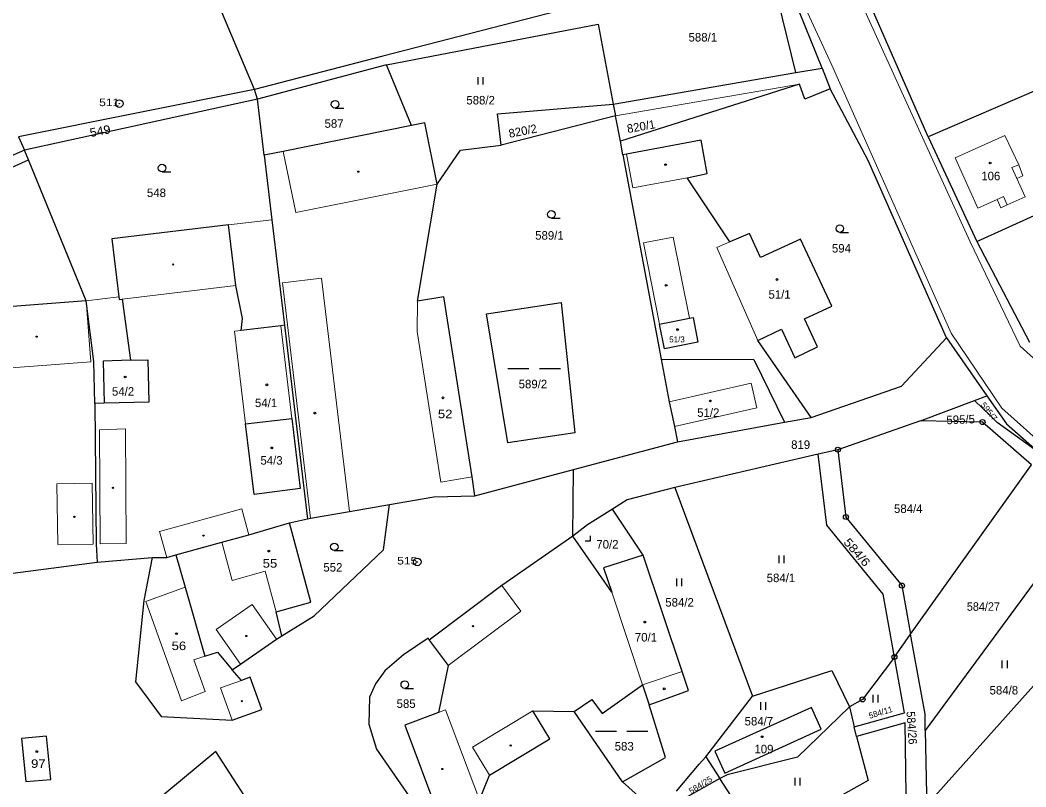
# Model space of a CAD drawing. Extents: x -687135 to -684370, y -1007309 to -1005782.
# Drawn here: x -685221.9 to -685021.3, y -1006597.5 to -1006444.6 of the extents above; entities that cross this region are included whole.
import ezdxf
from ezdxf.enums import TextEntityAlignment as Align

# ---------------------------------------------------------------- set-up
doc = ezdxf.new("R2010")
doc.units = 0
doc.header["$LTSCALE"] = 0.68
for name, color, linetype, lineweight in [('1', 7, 'Continuous', 25), ('3', 7, 'Continuous', 25), ('4', 7, 'Continuous', 13), ('5', 7, 'Continuous', 25), ('8', 7, 'Continuous', 25)]:
    doc.layers.add(name, color=color, linetype=linetype, lineweight=lineweight)
doc.layers.add('2', color=7, linetype='Continuous')

msp = doc.modelspace()

# ---------------------------------------------------------------- linework, layer by layer
at = {"layer": '1'}
for p, q in [((-685148.86, -1006453.5), (-685174.56, -1006460.29)), ((-685143.83, -1006465.57), (-685148.86, -1006453.5)), ((-685067.19, -1006455.02), (-685061.94, -1006454.16)), ((-685061.94, -1006454.16), (-685060.36, -1006458.25)), ((-685103.6, -1006461.29), (-685067.19, -1006455.02)), ((-685174.56, -1006460.29), (-685175.13, -1006458.36)), ((-685103.6, -1006461.29), (-685103.16, -1006463.61)), ((-685208.75, -1006500.55), (-685220.24, -1006472.43)), ((-685031.08, -1006488.72), (-685020.6, -1006508.76)), ((-685131.76, -1006535.66), (-685136.46, -1006505.64)), ((-685037.16, -1006507.9), (-685029.1, -1006519.47)), ((-685042.37, -1006524.46), (-685031.56, -1006520.39)), ((-685031.56, -1006520.39), (-685029.1, -1006519.47)), ((-685069.43, -1006524.75), (-685064.12, -1006523.78)), ((-685090.83, -1006528.68), (-685069.43, -1006524.75)), ((-685058.8, -1006530.22), (-685062.72, -1006531.12)), ((-685111.66, -1006547.46), (-685111.55, -1006534.15)), ((-685044.3, -1006567.02), (-685020.17, -1006533.22)), ((-685091.34, -1006537.79), (-685075.81, -1006579.35)), ((-685097.63, -1006551.25), (-685103.73, -1006542.09)), ((-685237.76, -1006556.75), (-685206.53, -1006552.66)), ((-685097.63, -1006551.25), (-685105.53, -1006553.81)), ((-685047.55, -1006571.57), (-685044.3, -1006567.02)), ((-685055.1, -1006587.45), (-685055.58, -1006585.5)), ((-685150.81, -1006589.92), (-685141.03, -1006604.08)), ((-685085.12, -1006591.49), (-685082.35, -1006595.77))]:
    msp.add_line(p, q, dxfattribs=at)
for points in [[(-685061.94, -1006454.16), (-685073.28, -1006426.13), (-685089.64, -1006391.69), (-685115.59, -1006335.15), (-685153.62, -1006286.74), (-685198.1, -1006232.27)], [(-685175.13, -1006458.36), (-685198.89, -1006402.17), (-685211.49, -1006378.14), (-685237.4, -1006328.81), (-685256.82, -1006291)], [(-685040.8, -1006467.83), (-685055.26, -1006434.88), (-685055.37, -1006434.63), (-685067.76, -1006407.52), (-685091.4, -1006354.8)], [(-685075.56, -1006429.52), (-685105.97, -1006440.47), (-685149.59, -1006451.75), (-685175.13, -1006458.36)], [(-685067.19, -1006455.02), (-685070.72, -1006440.65), (-685075.56, -1006429.52)], [(-685148.86, -1006453.5), (-685138.1, -1006451.42), (-685106.63, -1006445.33), (-685103.6, -1006461.29)], [(-685175.13, -1006458.36), (-685222.19, -1006467.84), (-685221, -1006470.47)], [(-685060.36, -1006458.25), (-685065.42, -1006460.34), (-685066.46, -1006457.32), (-685102.19, -1006468.71)], [(-685037.16, -1006507.9), (-685052.76, -1006472.57), (-685060.36, -1006458.25)], [(-685018.29, -1006458.13), (-685040.8, -1006467.83), (-685031.08, -1006488.72)], [(-685031.08, -1006488.72), (-685008.96, -1006478.66), (-685011.5, -1006472.51), (-685014.97, -1006465.08), (-685018.29, -1006458.13)], [(-685173.22, -1006471.51), (-685174.56, -1006460.29), (-685221, -1006470.47)], [(-685125.95, -1006469.47), (-685126.69, -1006463.23), (-685103.6, -1006461.29)], [(-685101.69, -1006471.4), (-685102.19, -1006468.71), (-685103.16, -1006463.61), (-685125.95, -1006469.47)], [(-685143.83, -1006465.57), (-685169.41, -1006470.74), (-685173.22, -1006471.51)], [(-685138.72, -1006477.24), (-685141.19, -1006465.03), (-685143.83, -1006465.57)], [(-685138.72, -1006477.24), (-685134.1, -1006470.5), (-685125.95, -1006469.47)], [(-685064.12, -1006523.78), (-685074.79, -1006508.43), (-685070.03, -1006506.22), (-685067.4, -1006511.89), (-685062.86, -1006509.68), (-685065.44, -1006504.1), (-685060.04, -1006501.59), (-685066.25, -1006488.21), (-685074.23, -1006491.91), (-685076.46, -1006487.1), (-685080.34, -1006488.79), (-685088.89, -1006475.98), (-685084.85, -1006475.12), (-685086.1, -1006468.46), (-685100.98, -1006471.27), (-685101.69, -1006471.4), (-685094.08, -1006512.2)], [(-685297.67, -1006530.98), (-685303.55, -1006523.96), (-685308.68, -1006511.71), (-685278.74, -1006498.76), (-685220.24, -1006472.43), (-685221, -1006470.47), (-685309.69, -1006509.25)], [(-685173.22, -1006471.51), (-685171.69, -1006484.35), (-685169.18, -1006505.42)], [(-685136.46, -1006505.64), (-685137.38, -1006499.75), (-685142.68, -1006500.57), (-685138.72, -1006477.24)], [(-685169.18, -1006505.42), (-685169.93, -1006505.51), (-685177.79, -1006506.45), (-685177.54, -1006504.08), (-685178.9, -1006497.49), (-685180.34, -1006485.38), (-685203.58, -1006488.15), (-685202.19, -1006499.77), (-685202.13, -1006500.26), (-685201.52, -1006500.19), (-685199.9, -1006512.39)], [(-685208.75, -1006500.55), (-685228.69, -1006502.07), (-685227.76, -1006514.23), (-685249.22, -1006517.08), (-685248.8, -1006521.04), (-685247.95, -1006529), (-685250.93, -1006529.31), (-685250.4, -1006534.39), (-685247.53, -1006534.08), (-685246.66, -1006544.7), (-685241.08, -1006544.24), (-685238.81, -1006544.06), (-685237.76, -1006556.75)], [(-685206.99, -1006521.01), (-685207.18, -1006512.65), (-685208.75, -1006500.55)], [(-685169.18, -1006505.42), (-685165.51, -1006536.24), (-685165.31, -1006537.9), (-685164.59, -1006543.99)], [(-685064.12, -1006523.78), (-685046.13, -1006517.55), (-685037.16, -1006507.9)], [(-685199.9, -1006512.39), (-685196.42, -1006512.31), (-685196.23, -1006520.76), (-685205.15, -1006520.97), (-685206.99, -1006521.01)], [(-685199.9, -1006512.39), (-685205.36, -1006512.59), (-685205.15, -1006520.97)], [(-685094.08, -1006512.2), (-685075.55, -1006512.24), (-685069.43, -1006524.75)], [(-685094.08, -1006512.2), (-685092.49, -1006520.7), (-685091.39, -1006525.58), (-685090.83, -1006528.68)], [(-685018.5, -1006531), (-685027.04, -1006524.82), (-685028.47, -1006523.43), (-685031.56, -1006520.39)], [(-685029.1, -1006519.47), (-685025.2, -1006525.08), (-685018.5, -1006531)], [(-685206.99, -1006521.01), (-685206.74, -1006549.07), (-685206.53, -1006552.66), (-685195.59, -1006551.7)], [(-685020.17, -1006533.22), (-685029.97, -1006524.71), (-685042.37, -1006524.46), (-685058.8, -1006530.22)], [(-685131.23, -1006539.41), (-685111.55, -1006534.15), (-685090.83, -1006528.68)], [(-685058.8, -1006530.22), (-685057.2, -1006543.65), (-685046.04, -1006557.33), (-685044.3, -1006567.02)], [(-685047.55, -1006571.57), (-685049.79, -1006559.07), (-685061.04, -1006545.28), (-685062.72, -1006531.12), (-685091.34, -1006537.79)], [(-685148.21, -1006541.16), (-685139.38, -1006539.64), (-685131.23, -1006539.41), (-685131.76, -1006535.66)], [(-685091.34, -1006537.79), (-685100.83, -1006540.25), (-685103.73, -1006542.09)], [(-685169.73, -1006567.35), (-685163.26, -1006563.34), (-685149.42, -1006550.2), (-685148.21, -1006541.16)], [(-685164.59, -1006543.99), (-685163.99, -1006543.89), (-685156.24, -1006542.55), (-685148.21, -1006541.16)], [(-685103.73, -1006542.09), (-685108.74, -1006545.21), (-685111.66, -1006547.46)], [(-685190.81, -1006551.2), (-685181.65, -1006548.68), (-685176.26, -1006547.19), (-685168.18, -1006544.84), (-685164.59, -1006543.99)], [(-685169.73, -1006567.35), (-685170.82, -1006562.59), (-685163.9, -1006560.64), (-685168.18, -1006544.84)], [(-685111.66, -1006547.46), (-685125.86, -1006557.33), (-685140.33, -1006568.19), (-685136.52, -1006573.27)], [(-685105.53, -1006553.81), (-685103.92, -1006558.64), (-685111.66, -1006547.46)], [(-685002.92, -1006558.42), (-685014.29, -1006549.41), (-685041.44, -1006586.25)], [(-685195.59, -1006551.7), (-685197.23, -1006560.28), (-685198.87, -1006576.51), (-685193.77, -1006583.42), (-685179.58, -1006584.2)], [(-685195.59, -1006551.7), (-685192.65, -1006551.71), (-685190.81, -1006551.2)], [(-685190.81, -1006551.2), (-685188.98, -1006557.66), (-685185.09, -1006571.39), (-685182.55, -1006570.59), (-685179.58, -1006574.1), (-685177.96, -1006573.02), (-685170.77, -1006568.02), (-685169.73, -1006567.35)], [(-685096.44, -1006581.08), (-685088.63, -1006578.28), (-685089.9, -1006574.48), (-685097.63, -1006551.25)], [(-684996.13, -1006550.77), (-684999.43, -1006554.36), (-685002.92, -1006558.42), (-685041.12, -1006601.16), (-685045.06, -1006605.58), (-685083.94, -1006649.24), (-685059.06, -1006657.45)], [(-685140.33, -1006568.19), (-685140.5, -1006567.81), (-685145.45, -1006571.13), (-685149.16, -1006574.34), (-685151.04, -1006576.95), (-685152.2, -1006579.61), (-685152.37, -1006584.97), (-685150.81, -1006589.92)], [(-685041.44, -1006586.25), (-685041.44, -1006582.95), (-685044.3, -1006567.02)], [(-685047.55, -1006571.57), (-685053.9, -1006580.03), (-685056.5, -1006581.51), (-685055.58, -1006585.5)], [(-685055.58, -1006585.5), (-685045.55, -1006582.69), (-685047.55, -1006571.57)], [(-685176.02, -1006575.61), (-685177.77, -1006576.24), (-685179.58, -1006574.1)], [(-685136.52, -1006573.27), (-685138.48, -1006582.66), (-685145.19, -1006585.18), (-685138.46, -1006603.11), (-685141.03, -1006604.08), (-685139.08, -1006606.35)], [(-685075.81, -1006579.35), (-685060.03, -1006574.27), (-685056.5, -1006581.51)], [(-685179.58, -1006584.2), (-685173.66, -1006582.02), (-685176.02, -1006575.61)], [(-685111.41, -1006582.43), (-685107.86, -1006580.04), (-685105.81, -1006582.86), (-685097.77, -1006577.1), (-685096.44, -1006581.08)], [(-685091.03, -1006598.36), (-685086.48, -1006592.94), (-685085.12, -1006591.49), (-685075.81, -1006579.35)], [(-685139.08, -1006606.35), (-685129.32, -1006602.68), (-685130.31, -1006600.05), (-685128.27, -1006595.15), (-685116.28, -1006587.91), (-685119.66, -1006582.31), (-685111.41, -1006582.43)], [(-685114.27, -1006630.81), (-685112.12, -1006623.52), (-685094.72, -1006602.76), (-685101.78, -1006596.46), (-685111.41, -1006582.43)], [(-685101.78, -1006596.46), (-685093.18, -1006591.61), (-685096.44, -1006581.08)], [(-685056.5, -1006581.51), (-685066.84, -1006591.55), (-685080.9, -1006595.06), (-685082.35, -1006595.77)], [(-685045.06, -1006605.58), (-685045.17, -1006598.99), (-685045.41, -1006584.73), (-685055.1, -1006587.45)], [(-685041.44, -1006586.25), (-685041.16, -1006598.92), (-685041.12, -1006601.16)], [(-685055.1, -1006587.45), (-685052.79, -1006596.21), (-685074.3, -1006608.24), (-685082.35, -1006595.77)], [(-685082.35, -1006595.77), (-685089.83, -1006600), (-685077.97, -1006616.25), (-685045.06, -1006605.58)]]:
    msp.add_lwpolyline(points, dxfattribs=at)
for points in [[(-685128.9, -1006503.1), (-685113.97, -1006500.84), (-685111.3, -1006526.86), (-685124.6, -1006528.84)], [(-685088.43, -1006504), (-685087.7, -1006503.86), (-685086.73, -1006508.76), (-685093.39, -1006510.08), (-685094.36, -1006505.18)], [(-685176.92, -1006525.1), (-685167.72, -1006524), (-685166.05, -1006537.99), (-685175.25, -1006539.14)], [(-685083.36, -1006590.32), (-685081.36, -1006594.72), (-685062.12, -1006585.98), (-685064.1, -1006581.64)], [(-685216.63, -1006587.39), (-685221.6, -1006587.8), (-685220.76, -1006596.41), (-685215.78, -1006596.02)], [(-685206.33, -1006609.89), (-685195.79, -1006616.98), (-685175.8, -1006601.34), (-685182.89, -1006590.44)]]:
    msp.add_lwpolyline(points, close=True, dxfattribs=at)
at = {"layer": '3'}
for p, q in [((-685130.581, -1006457.4), (-685130.581, -1006455.9)), ((-685129.58, -1006457.4), (-685129.58, -1006455.9)), ((-685159.093, -1006462.09), (-685157.343, -1006462.09)), ((-685193.593, -1006474.8), (-685191.843, -1006474.8)), ((-685115.953, -1006484.05), (-685114.203, -1006484.05)), ((-685058.423, -1006486.88), (-685056.673, -1006486.88)), ((-685124.613, -1006514.03), (-685120.413, -1006514.03)), ((-685118.312, -1006514.03), (-685114.112, -1006514.03)), ((-685159.233, -1006550.35), (-685157.483, -1006550.35)), ((-685070.541, -1006552.85), (-685070.541, -1006551.35)), ((-685069.54, -1006552.85), (-685069.54, -1006551.35)), ((-685090.921, -1006557.41), (-685090.921, -1006555.91)), ((-685089.92, -1006557.41), (-685089.92, -1006555.91)), ((-685026.021, -1006573.78), (-685026.021, -1006572.28)), ((-685025.02, -1006573.78), (-685025.02, -1006572.28)), ((-685145.183, -1006577.82), (-685143.433, -1006577.82)), ((-685074.161, -1006582.09), (-685074.161, -1006580.59)), ((-685073.16, -1006582.09), (-685073.16, -1006580.59)), ((-685051.771, -1006580.62), (-685051.771, -1006579.12)), ((-685050.77, -1006580.62), (-685050.77, -1006579.12)), ((-685107.183, -1006586.35), (-685102.983, -1006586.35)), ((-685100.882, -1006586.35), (-685096.682, -1006586.35)), ((-685067.331, -1006597.17), (-685067.331, -1006595.67)), ((-685066.33, -1006597.17), (-685066.33, -1006595.67))]:
    msp.add_line(p, q, dxfattribs=at)
msp.add_lwpolyline([(-685109.181, -1006548.38), (-685108.18, -1006548.38), (-685108.18, -1006547.38)], dxfattribs=at)
for centre in [(-685159.0929, -1006461.3398), (-685193.5929, -1006474.0498), (-685115.9529, -1006483.2998), (-685058.4229, -1006486.1298), (-685159.2329, -1006549.5998), (-685145.1829, -1006577.0698)]:
    msp.add_circle(centre, 0.75, dxfattribs=at)
at = {"layer": '4'}
for p, q in [((-685103.16, -1006463.61), (-685066.46, -1006457.32)), ((-685025.53, -1006467.53), (-685035.4, -1006471.99)), ((-685025.53, -1006467.53), (-685022.74, -1006473.44)), ((-685166.94, -1006482.94), (-685169.41, -1006470.74)), ((-685100.98, -1006471.27), (-685099.72, -1006478.02)), ((-685035.4, -1006471.99), (-685030.88, -1006482.05)), ((-685021.93, -1006475.62), (-685022.74, -1006473.44)), ((-685088.89, -1006475.98), (-685099.72, -1006478.02)), ((-685023.12, -1006476.15), (-685021.93, -1006475.62)), ((-685138.72, -1006477.24), (-685166.94, -1006482.94)), ((-685030.88, -1006482.05), (-685027.05, -1006480.33)), ((-685027.05, -1006480.33), (-685025.77, -1006479.76)), ((-685027.05, -1006480.33), (-685026.31, -1006481.97)), ((-685025.03, -1006481.4), (-685021.48, -1006479.8)), ((-685180.34, -1006485.38), (-685171.69, -1006484.35)), ((-685097.57, -1006488.99), (-685091.64, -1006487.81)), ((-685088.43, -1006504), (-685091.64, -1006487.81)), ((-685097.57, -1006488.99), (-685094.36, -1006505.18)), ((-685082.96, -1006489.93), (-685080.34, -1006488.79)), ((-685082.96, -1006489.93), (-685074.79, -1006508.43)), ((-685169.59, -1006496.95), (-685161.78, -1006496.02)), ((-685161.78, -1006496.02), (-685156.24, -1006542.55)), ((-685201.52, -1006500.19), (-685178.9, -1006497.49)), ((-685163.99, -1006543.89), (-685169.59, -1006496.95)), ((-685208.75, -1006500.55), (-685202.19, -1006499.77)), ((-685208.75, -1006500.55), (-685207.82, -1006512.71)), ((-685142.68, -1006500.57), (-685142.73, -1006506.62)), ((-685177.79, -1006506.45), (-685179.12, -1006506.61)), ((-685167.72, -1006524), (-685169.93, -1006505.51)), ((-685179.12, -1006506.61), (-685176.92, -1006525.1)), ((-685138.02, -1006536.7), (-685142.73, -1006506.62)), ((-685207.82, -1006512.71), (-685227.76, -1006514.23)), ((-685092.49, -1006520.7), (-685076.12, -1006516.94)), ((-685026.12, -1006521.97), (-684994.58, -1006550.04)), ((-685206.06, -1006526.27), (-685200.87, -1006526.05)), ((-685205.94, -1006549.01), (-685206.06, -1006526.27)), ((-685200.87, -1006526.05), (-685200.74, -1006548.93)), ((-685138.02, -1006536.7), (-685131.76, -1006535.66)), ((-685207.54, -1006536.89), (-685214.59, -1006537)), ((-685214.59, -1006537), (-685214.39, -1006549.15)), ((-685207.54, -1006536.89), (-685207.34, -1006549.04)), ((-685177.7, -1006541.99), (-685176.39, -1006546.71)), ((-685181.65, -1006548.68), (-685179.58, -1006556.32)), ((-685176.39, -1006546.71), (-685176.26, -1006547.19)), ((-685207.34, -1006549.04), (-685214.39, -1006549.15)), ((-685200.74, -1006548.93), (-685205.94, -1006549.01)), ((-685192.78, -1006551.23), (-685192.65, -1006551.71)), ((-685173.02, -1006554.48), (-685179.58, -1006556.32)), ((-685173.02, -1006554.48), (-685170.82, -1006562.59)), ((-685188.98, -1006557.66), (-685196.82, -1006560.48)), ((-685125.86, -1006557.33), (-685122.05, -1006562.41)), ((-685097.77, -1006577.1), (-685103.92, -1006558.64)), ((-685182.77, -1006566.1), (-685175.59, -1006561.1)), ((-685170.77, -1006568.02), (-685175.59, -1006561.1)), ((-685136.52, -1006573.27), (-685122.05, -1006562.41)), ((-685177.96, -1006573.02), (-685182.77, -1006566.1)), ((-685097.77, -1006577.1), (-685089.9, -1006574.48)), ((-685181.95, -1006577.74), (-685177.77, -1006576.24)), ((-685179.58, -1006584.2), (-685181.95, -1006577.74)), ((-685138.48, -1006582.66), (-685137.04, -1006582.12)), ((-685130.31, -1006600.05), (-685137.04, -1006582.12)), ((-685119.66, -1006582.31), (-685131.65, -1006589.55)), ((-685131.65, -1006589.55), (-685128.27, -1006595.15))]:
    msp.add_line(p, q, dxfattribs=at)
for points in [[(-685090.32, -1006387.84), (-685060, -1006453.51), (-685036.24, -1006506.98), (-685026.12, -1006521.97)], [(-685065.37, -1006416.52), (-685042.68, -1006466.37), (-685032.4, -1006488.74), (-685022.44, -1006509.59), (-684967.45, -1006559.07), (-684916.25, -1006603.35), (-684856.74, -1006654.98), (-684782.53, -1006719.91)], [(-685021.48, -1006479.8), (-685023.12, -1006476.15), (-685024.1, -1006473.97), (-685022.74, -1006473.44)], [(-685026.31, -1006481.97), (-685025.03, -1006481.4), (-685025.77, -1006479.76)], [(-685076.12, -1006516.94), (-685075, -1006521.87), (-685091.39, -1006525.58)], [(-685192.78, -1006551.23), (-685194.08, -1006546.51), (-685177.7, -1006541.99)], [(-685196.82, -1006560.48), (-685189.69, -1006580.3), (-685184.99, -1006578.42)], [(-685185.09, -1006571.39), (-685187.24, -1006572.16), (-685184.99, -1006578.42)]]:
    msp.add_lwpolyline(points, dxfattribs=at)
at = {"layer": '5'}
for centre, radius in [((-685093.1668, -1006473.3792), 0.175), ((-685028.4668, -1006473.0492), 0.175), ((-685154.4548, -1006474.7794), 0.1225), ((-685191.3848, -1006493.2994), 0.1225), ((-685070.9468, -1006496.2892), 0.175), ((-685093.0568, -1006497.4492), 0.175), ((-685090.7868, -1006506.2692), 0.175), ((-685218.5848, -1006507.6894), 0.1225), ((-685200.9368, -1006515.7192), 0.175), ((-685172.6768, -1006517.2892), 0.175), ((-685137.5568, -1006519.8792), 0.175), ((-685084.2468, -1006520.4892), 0.175), ((-685163.1268, -1006522.9292), 0.175), ((-685171.7168, -1006529.8692), 0.175), ((-685203.3548, -1006537.8294), 0.1225), ((-685211.0748, -1006543.6194), 0.1225), ((-685185.3348, -1006547.3694), 0.1225), ((-685172.3068, -1006550.4492), 0.175), ((-685097.3268, -1006564.5992), 0.175), ((-685131.5948, -1006565.4194), 0.1225), ((-685190.7068, -1006566.9192), 0.175), ((-685176.7748, -1006567.3794), 0.1225), ((-685093.4468, -1006577.9092), 0.175), ((-685177.6848, -1006580.3894), 0.1225), ((-685073.9068, -1006587.4792), 0.175), ((-685218.5468, -1006590.4292), 0.175), ((-685124.0548, -1006589.2194), 0.1225), ((-685137.7048, -1006593.8994), 0.1225)]:
    msp.add_circle(centre, radius, dxfattribs=at)
at = {"layer": '8'}
for centre, radius in [((-685202.12, -1006461.2098), 0.75), ((-685202.12, -1006461.2098), 0.03), ((-685029.97, -1006524.7099), 0.5), ((-685029.97, -1006524.7099), 0.0303), ((-685058.8, -1006530.2199), 0.5), ((-685058.8, -1006530.2199), 0.0303), ((-685057.2, -1006543.6499), 0.5), ((-685057.2, -1006543.6499), 0.0303), ((-685142.69, -1006552.6198), 0.75), ((-685142.69, -1006552.6198), 0.03), ((-685046.04, -1006557.3299), 0.5), ((-685046.04, -1006557.3299), 0.0303), ((-685047.55, -1006571.5699), 0.5), ((-685047.55, -1006571.5699), 0.0303), ((-685053.9, -1006580.0299), 0.5), ((-685053.9, -1006580.0299), 0.0303)]:
    msp.add_circle(centre, radius, dxfattribs=at)

# ---------------------------------------------------------------- texts
at = {"layer": '2'}
for s, height, p in [('588/1', 1.7, (-685088.59, -1006448.82)), ('588/2', 1.7, (-685132.9, -1006461.37)), ('587', 1.7, (-685161.18, -1006466.02)), ('106', 1.7, (-685030.21, -1006476.49)), ('548', 1.7, (-685196.6, -1006479.84)), ('589/1', 1.7, (-685119.18, -1006488.34)), ('594', 1.7, (-685060, -1006490.91)), ('51/1', 1.7, (-685072.66, -1006500.11)), ('51/3', 1.19, (-685092.45, -1006508.825)), ('589/2', 1.7, (-685122.47, -1006517.98)), ('54/2', 1.7, (-685203.58, -1006519.46)), ('54/1', 1.7, (-685175.06, -1006521.73)), ('51/2', 1.7, (-685086.87, -1006523.679)), ('819', 1.7, (-685068.14, -1006530.07)), ('54/3', 1.7, (-685173.97, -1006533.21)), ('584/4', 1.7, (-685047.62, -1006542.84)), ('70/2', 1.7, (-685106.98, -1006549.94)), ('552', 1.7, (-685161.42, -1006554.53)), ('584/1', 1.7, (-685073.01, -1006556.64)), ('584/2', 1.7, (-685093.23, -1006561.52)), ('70/1', 1.7, (-685099.3, -1006568.49)), ('584/8', 1.7, (-685028.56, -1006579.039)), ('585', 1.7, (-685146.81, -1006581.73)), ('584/7', 1.7, (-685077.41, -1006585.22)), ('583', 1.7, (-685103.32, -1006590.22)), ('109', 1.7, (-685075.46, -1006590.78))]:
    msp.add_text(s, height=height, dxfattribs=at).set_placement(p)
for s, height, rotation, width, p in [('549', 1.7, 11, 1.1, (-685207.827, -1006467.884)), ('584/6', 1.7, 311, 1.15, (-685057.791, -1006548.777)), ('584/26', 1.7, 274, 0.95, (-685045.147, -1006582.459)), ('584/25', 1.19, 32, 1.05, (-685088.064, -1006598.954))]:
    msp.add_text(s, height=height, rotation=rotation, dxfattribs=dict(at, width=width)).set_placement(p)
for s, height, rotation, p in [('820/2', 1.7, 11, (-685124.287, -1006468.034)), ('820/1', 1.7, 10, (-685100.712, -1006467.087)), ('595/5', 1.7, 2, (-685037.14, -1006525.159)), ('584/11', 1.19, 17, (-685052.436, -1006583.899))]:
    msp.add_text(s, height=height, rotation=rotation, dxfattribs=at).set_placement(p)
for s, width, p in [('52', 1.15, (-685138.58, -1006523.94)), ('55', 1.15, (-685173.52, -1006553.75)), ('584/27', 0.95, (-685033.1, -1006562.35)), ('56', 1.15, (-685191.69, -1006570.19)), ('97', 1.15, (-685219.71, -1006593.679))]:
    msp.add_text(s, height=1.7, dxfattribs=dict(at, width=width)).set_placement(p)
at = {"layer": '2', "width": 1.1}
msp.add_text('595/7', height=1.139, rotation=308, dxfattribs=at).set_placement((-685029.1055, -1006522.9439), align=Align.CENTER)
at = {"layer": '8', "width": 1.2}
for s, p in [('511', (-685202.12, -1006461.71)), ('515', (-685142.69, -1006553.12))]:
    msp.add_text(s, height=1.5, dxfattribs=at).set_placement(p, align=Align.RIGHT)

doc.saveas('drawing.dxf')
